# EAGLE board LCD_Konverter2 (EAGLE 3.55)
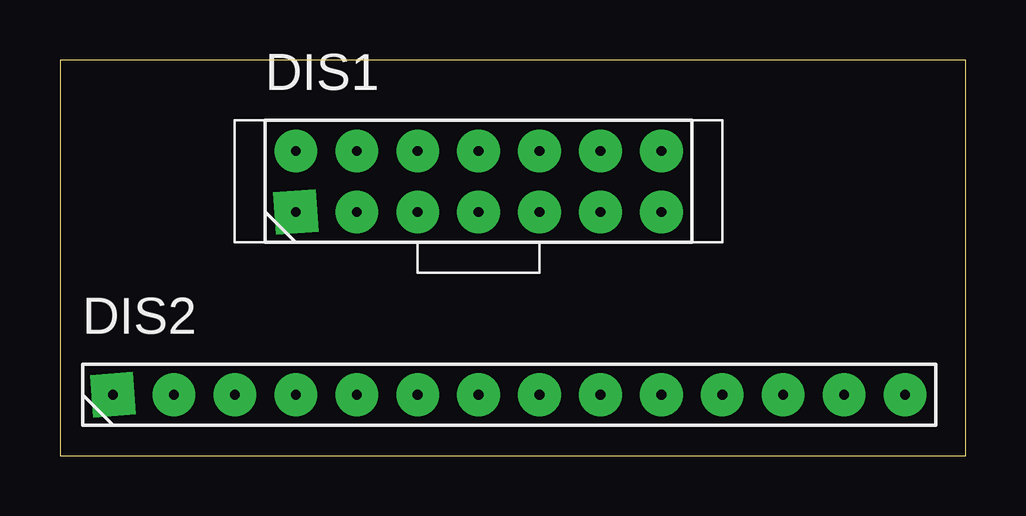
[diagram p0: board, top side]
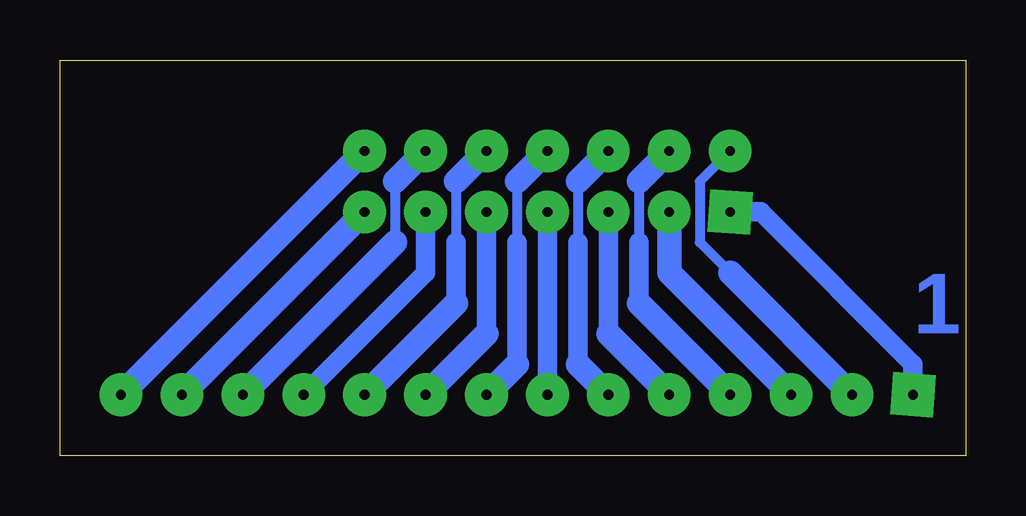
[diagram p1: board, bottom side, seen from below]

Size 37.77 x 16.49 mm. Coordinates in mm from the lower left corner, seen from the top.
Outline: 37.77,0 37.77,16.49 0,16.49 0,0 37.77,0
Copper layers used: Bottom

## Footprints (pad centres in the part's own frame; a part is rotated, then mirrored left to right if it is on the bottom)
7 = drill 0.406 pad 1.778 square:  0,0 | drill 0.406 pad 1.778 round:  2.54,0;  5.08,0;  7.62,0;  10.16,0;  10.16,2.54;  7.62,2.54;  5.08,2.54;  2.54,2.54;  0,2.54;  12.7,0;  12.7,2.54;  15.24,0;  15.24,2.54
14 = drill 0.406 pad 1.778 square:  0,0 | drill 0.406 pad 1.778 round:  5.08,0;  10.16,0;  15.24,0;  20.32,0;  22.86,0;  17.78,0;  12.7,0;  7.62,0;  2.54,0;  25.4,0;  27.94,0;  30.48,0;  33.02,0

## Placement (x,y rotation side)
DIS1  LCD_DOPPEL  [7]  9.83,10.16 0 top
DIS2  LCD_EIREIH  [14]  2.21,2.54 0 top

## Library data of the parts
DIS1 DIS2 = holg_plt

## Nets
N$1: DIS1. DIS2.
N$2: DIS1. DIS2.
N$3: DIS1. DIS2.
N$4: DIS1. DIS2.
N$5: DIS1. DIS2.
N$6: DIS1. DIS2.
N$7: DIS1. DIS2.
N$8: DIS1. DIS2.
N$9: DIS1. DIS2.
N$10: DIS1. DIS2.
N$11: DIS1. DIS2.
N$12: DIS1. DIS2.
N$13: DIS1. DIS2.
N$14: DIS1. DIS2.

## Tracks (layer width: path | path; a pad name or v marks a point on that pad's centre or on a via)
N$1
  Bottom 0.813: 9.83,10.16 8.56,10.16 2.21,3.81 2.21,2.54
N$2
  Bottom 0.406: 9.83,12.7 11.1,11.43 11.1,8.89 9.83,7.62
  Bottom 1.016: 4.75,2.54 9.83,7.62
N$3
  Bottom 1.016: 12.37,10.16 12.37,7.62 7.29,2.54
N$4
  Bottom 0.406: 13.64,11.43 13.64,8.89
  Bottom 0.813: 13.64,6.35 13.64,8.89
  Bottom 1.016: 12.37,12.7 13.64,11.43 | 13.64,6.35 9.83,2.54
N$5
  Bottom 0.813: 14.91,10.16 14.91,5.08
  Bottom 1.016: 14.91,5.08 12.37,2.54
N$6
  Bottom 0.406: 16.18,11.43 16.18,8.89
  Bottom 0.813: 16.18,3.81 16.18,8.89
  Bottom 1.016: 14.91,12.7 16.18,11.43 | 16.18,3.81 14.91,2.54
N$7
  Bottom 0.813: 17.45,10.16 17.45,2.54
N$8
  Bottom 0.406: 18.72,11.43 18.72,8.89
  Bottom 0.813: 18.72,3.81 18.72,8.89
  Bottom 1.016: 17.45,12.7 18.72,11.43 | 18.72,3.81 19.99,2.54
N$9
  Bottom 0.813: 19.99,10.16 19.99,5.08
  Bottom 1.016: 19.99,5.08 22.53,2.54
N$10
  Bottom 0.406: 21.26,11.43 21.26,8.89
  Bottom 0.813: 21.26,6.35 21.26,8.89
  Bottom 1.016: 19.99,12.7 21.26,11.43 | 21.26,6.35 25.07,2.54
N$11
  Bottom 0.813: 22.53,10.16 22.53,7.62 27.61,2.54
N$12
  Bottom 0.406: 23.8,11.43 23.8,8.89
  Bottom 1.016: 22.53,12.7 23.8,11.43 | 23.8,8.89 30.15,2.54
N$13
  Bottom 1.016: 25.07,10.16 32.69,2.54
N$14
  Bottom 1.016: DIS1. DIS2.

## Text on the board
Bottom: 1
